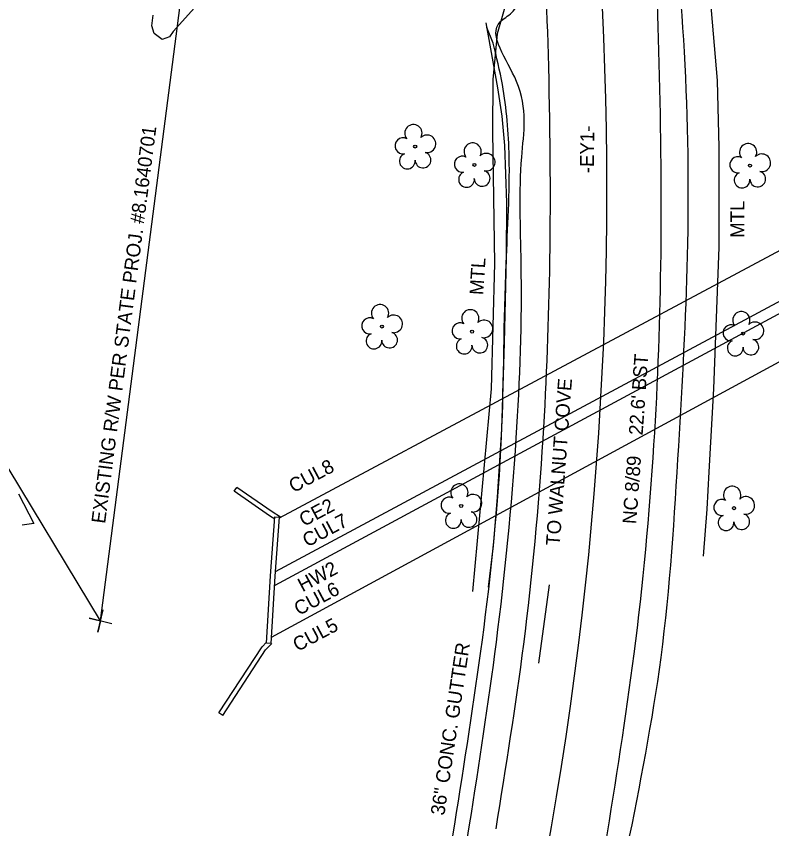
# Model space of a CAD drawing. Extents: x 1645945 to 2447332, y 713118 to 970361.
# Drawn here: x 1646189.7 to 1646352.4, y 969127.2 to 969302.2 of the extents above; entities that cross this region are included whole.
import ezdxf

# ---------------------------------------------------------------- set-up
doc = ezdxf.new("R2010")
doc.units = 0
for name, color, linetype in [('Exist Guardrail', 7, 'Continuous'), ('Exist Guardrail Text', 7, 'Continuous'), ('Exist Horizontal Alignment', 7, 'Continuous'), ('Exist Horizontal Alignment Direction Label', 7, 'Continuous'), ('Exist Property Corner CELL', 7, 'Continuous'), ('Exist Property Line', 7, 'Continuous'), ('Exist Property Line Leader', 7, 'Continuous'), ('Exist Right of Way Line', 7, 'Continuous'), ('Exist Right of Way Line Text', 7, 'Continuous'), ('Exist Roads Curbs', 7, 'Continuous'), ('Exist Roads Curbs Text', 7, 'Continuous'), ('Exist Roads EOP', 7, 'Continuous'), ('Exist Roads EOT', 7, 'Continuous'), ('Exist Roads EOT Leader', 7, 'Continuous'), ('Exist Roads EOT Text', 7, 'Continuous'), ('Exist Structure Major Box Culvert or Tunnel Topo', 7, 'Continuous'), ('Exist Structure Major Bridge WW', 7, 'Continuous'), ('Exist Structure Major Bridge WW Text', 7, 'Continuous'), ('Exist Utilities Telephone UG FO SUE LOS C', 7, 'Continuous'), ('Exist Vegetation Tree CELL', 7, 'Continuous'), ('Exist Vegetation Woods Line', 7, 'Continuous')]:
    doc.layers.add(name, color=color, linetype=linetype)

msp = doc.modelspace()

# ---------------------------------------------------------------- linework, layer by layer
at = {"layer": 'Exist Guardrail'}
for points in [[(1646337.72, 969322.79), (1646339.59, 969300.91), (1646340.61, 969288.29), (1646341.03, 969273.88), (1646340.98, 969252.4), (1646339.88, 969221.89), (1646338.83, 969204.07), (1646338.44, 969196.02), (1646337.61, 969185.9)], [(1646291.41, 969179.21), (1646292.46, 969188.08), (1646293.35, 969198.61), (1646294.24, 969213.19), (1646294.85, 969231.85), (1646295.28, 969250.3), (1646295.35, 969261.96), (1646294.88, 969274.32), (1646294.34, 969280.63), (1646293.4, 969286.73), (1646290.88, 969300.77)]]:
    msp.add_lwpolyline(points, dxfattribs=at)
at = {"layer": 'Exist Horizontal Alignment'}
msp.add_arc((1645516.89, 969265.29), 800, 348.6692, 18.755, dxfattribs=at)
at = {"layer": 'Exist Property Corner CELL'}
msp.add_line((1646207.84, 969171.93), (1646207.84, 969171.93), dxfattribs=at)
msp.add_lwpolyline([(1646210.27, 969171.33), (1646205.41, 969172.53), (1646207.84, 969171.93), (1646207.24, 969169.5), (1646208.44, 969174.36)], dxfattribs=at)
at = {"layer": 'Exist Property Line'}
msp.add_line((1646207.84, 969171.93), (1646184.77, 969210.1), dxfattribs=at)
at = {"layer": 'Exist Property Line Leader'}
msp.add_lwpolyline([(1646190.2, 969199.33), (1646193.51, 969192.93), (1646190.96, 969192.56)], dxfattribs=at)
at = {"layer": 'Exist Right of Way Line'}
msp.add_line((1646207.84, 969171.93), (1646236.81, 969395.79), dxfattribs=at)
msp.add_line((1646207.84, 969171.93), (1646236.81, 969395.79), dxfattribs=at)
msp.add_line((1646207.84, 969171.93), (1646236.81, 969395.79), dxfattribs=at)
msp.add_line((1646207.84, 969171.93), (1646236.81, 969395.79), dxfattribs=at)
at = {"layer": 'Exist Roads Curbs'}
for p, q in [((1646292.43, 969296.35), (1646291.07, 969299.73)), ((1646282.51, 969118.14), (1646284.14, 969128.2))]:
    msp.add_line(p, q, dxfattribs=at)
msp.add_spline([(1646284.14, 969128.2), (1646290.07, 969167.89), (1646294.19, 969211.57), (1646295.19, 969248.95), (1646295.85, 969271.86), (1646294.38, 969287.43), (1646292.43, 969296.35)], degree=3, dxfattribs=at)
at = {"layer": 'Exist Roads EOP'}
msp.add_line((1646285.57, 969117.57), (1646287.33, 969128.01), dxfattribs=at)
for points in [[(1646287.33, 969128.01), (1646293.09, 969167.33), (1646297.37, 969211.3), (1646298.43, 969249.08), (1646298.55, 969271.82), (1646297.44, 969288.13), (1646293.89, 969300.95), (1646296.41, 969302.95), (1646298.17, 969306.12), (1646298.27, 969332.13), (1646295.51, 969374.21), (1646289.77, 969414.06), (1646284.35, 969440.07), (1646274.28, 969480.08), (1646260.88, 969521.84), (1646237.07, 969568.06), (1646226.33, 969574.21), (1646210.08, 969580.6)], [(1646379.88, 969432.02), (1646359.09, 969426.37), (1646353.34, 969423.7), (1646346.05, 969418.75), (1646333.89, 969406.7), (1646326.81, 969393.02), (1646325.09, 969385.45), (1646325.5, 969379.16), (1646330.03, 969336.13), (1646333.52, 969294.46), (1646334.18, 969250.57), (1646332.28, 969209.59), (1646328.48, 969164.09), (1646321.21, 969122.91)]]:
    msp.add_spline(points, degree=3, dxfattribs=at)
at = {"layer": 'Exist Roads EOT'}
for points in [[(1646352.39, 969425.32), (1646344.68, 969420.87), (1646331.6, 969408.76), (1646323.81, 969394.56), (1646321.79, 969386.09), (1646321.5, 969379.49), (1646325.71, 969335.59), (1646328.02, 969294.74), (1646328.47, 969250.99), (1646326.96, 969209.87), (1646322.68, 969164.82), (1646316.52, 969123.72)], [(1646293.03, 969127.18), (1646298.98, 969166.96), (1646303.15, 969211.21), (1646304.61, 969249.63), (1646304.29, 969293.94), (1646302.47, 969332.58), (1646298.43, 969374.41), (1646292.35, 969414.45)]]:
    msp.add_spline(points, degree=3, dxfattribs=at)
at = {"layer": 'Exist Roads EOT Leader'}
msp.add_line((1646302.24, 969162.81), (1646304.56, 969179.68), dxfattribs=at)
at = {"layer": 'Exist Structure Major Box Culvert or Tunnel Topo'}
for p, q in [((1646246.39, 969194.17), (1646400.28, 969276.43)), ((1646245.55, 969182.6), (1646399.69, 969265.26)), ((1646399.55, 969262.69), (1646245.35, 969179.57)), ((1646244.67, 969168.45), (1646399, 969252.16))]:
    msp.add_line(p, q, dxfattribs=at)
at = {"layer": 'Exist Structure Major Bridge WW'}
for p, q in [((1646236.6, 969199.86), (1646237.17, 969200.68)), ((1646245.4, 969194.36), (1646246.4, 969194.29)), ((1646244.59, 969167.1), (1646243.59, 969167.16)), ((1646234.19, 969151.59), (1646233.35, 969152.13))]:
    msp.add_line(p, q, dxfattribs=at)
for points in [[(1646246.63, 969194.27), (1646244.81, 969195.4), (1646237.17, 969200.68)], [(1646245.36, 969193.88), (1646244.26, 969194.57), (1646236.6, 969199.86)], [(1646243.59, 969167.16), (1646244.48, 969181.65), (1646245.4, 969194.36)], [(1646244.59, 969167.1), (1646245.47, 969181.58), (1646246.4, 969194.29)], [(1646233.35, 969152.13), (1646242.62, 969166.38), (1646243.6, 969167.34)], [(1646234.19, 969151.59), (1646243.4, 969165.74), (1646244.77, 969167.09)]]:
    msp.add_lwpolyline(points, dxfattribs=at)
at = {"layer": 'Exist Utilities Telephone UG FO SUE LOS C'}
msp.add_lwpolyline([(1646280.35, 969448.45), (1646284.77, 969427.42), (1646292.91, 969380.8), (1646296.99, 969335.53), (1646294.79, 969303.6), (1646293.24, 969298.34), (1646292.34, 969288.54), (1646292.24, 969277.3), (1646292.7, 969248.91), (1646291.99, 969221.91), (1646287.95, 969178.26)], dxfattribs=at)
at = {"layer": 'Exist Vegetation Tree CELL'}
for p, q in [((1646275.6, 969274.1), (1646275.6, 969274.1)), ((1646288.36, 969270.14), (1646288.36, 969270.14)), ((1646347.7, 969270.01), (1646347.7, 969270.01)), ((1646268.43, 969235.33), (1646268.43, 969235.33)), ((1646287.87, 969234.24), (1646287.87, 969234.24)), ((1646346.22, 969233.82), (1646346.22, 969233.82)), ((1646285.51, 969196.7), (1646285.51, 969196.7)), ((1646344.26, 969196.22), (1646344.26, 969196.22))]:
    msp.add_line(p, q, dxfattribs=at)
for centre in [(1646275.6, 969274.1), (1646288.36, 969270.14), (1646347.7, 969270.01), (1646268.43, 969235.33), (1646287.87, 969234.24), (1646346.22, 969233.82), (1646285.51, 969196.7), (1646344.26, 969196.22)]:
    msp.add_circle(centre, 0.326, dxfattribs=at)
for centre, radius, start, end in [((1646275.22, 969276.97), 1.86, 330.1651, 219.7134), ((1646273, 969274.25), 1.73, 62.6636, 279.3457), ((1646278.15, 969274.68), 1.9, 257.1011, 134.1999), ((1646287.98, 969273.02), 1.86, 330.1651, 219.7134), ((1646347.31, 969272.89), 1.86, 330.1651, 219.7134), ((1646273.9, 969270.97), 1.69, 111.5671, 6.231), ((1646277.28, 969271.2), 1.7, 181.2822, 74.56), ((1646290.91, 969270.73), 1.9, 257.1011, 134.1999), ((1646350.25, 969270.6), 1.9, 257.1011, 134.1999), ((1646285.76, 969270.3), 1.73, 62.6636, 279.3457), ((1646345.09, 969270.17), 1.73, 62.6636, 279.3457), ((1646290.04, 969267.24), 1.7, 181.2822, 74.56), ((1646286.66, 969267.02), 1.69, 111.5671, 6.231), ((1646346, 969266.89), 1.69, 111.5671, 6.231), ((1646349.37, 969267.11), 1.7, 181.2822, 74.56), ((1646268.04, 969238.2), 1.86, 330.1651, 219.7134), ((1646270.98, 969235.91), 1.9, 257.1011, 134.1999), ((1646287.48, 969237.11), 1.86, 330.1651, 219.7134), ((1646345.84, 969236.69), 1.86, 330.1651, 219.7134), ((1646265.82, 969235.48), 1.73, 62.6636, 279.3457), ((1646285.26, 969234.39), 1.73, 62.6636, 279.3457), ((1646290.42, 969234.83), 1.9, 257.1011, 134.1999), ((1646343.62, 969233.97), 1.73, 62.6636, 279.3457), ((1646348.77, 969234.41), 1.9, 257.1011, 134.1999), ((1646270.1, 969232.43), 1.7, 181.2822, 74.56), ((1646266.73, 969232.21), 1.69, 111.5671, 6.231), ((1646286.16, 969231.12), 1.69, 111.5671, 6.231), ((1646289.54, 969231.34), 1.7, 181.2822, 74.56), ((1646344.52, 969230.7), 1.69, 111.5671, 6.231), ((1646347.9, 969230.92), 1.7, 181.2822, 74.56), ((1646285.13, 969199.58), 1.86, 330.1651, 219.7134), ((1646343.87, 969199.09), 1.86, 330.1651, 219.7134), ((1646288.06, 969197.29), 1.9, 257.1011, 134.1999), ((1646282.91, 969196.86), 1.73, 62.6636, 279.3457), ((1646341.65, 969196.37), 1.73, 62.6636, 279.3457), ((1646346.81, 969196.81), 1.9, 257.1011, 134.1999), ((1646287.19, 969193.8), 1.7, 181.2822, 74.56), ((1646283.81, 969193.58), 1.69, 111.5671, 6.231), ((1646342.55, 969193.1), 1.69, 111.5671, 6.231), ((1646345.93, 969193.32), 1.7, 181.2822, 74.56)]:
    msp.add_arc(centre, radius, start, end, dxfattribs=at)
at = {"layer": 'Exist Vegetation Woods Line'}
msp.add_lwpolyline([(1646228.73, 969304.68), (1646223.51, 969298.9), (1646222.69, 969297.7), (1646221.1, 969297.18), (1646219.39, 969298.43), (1646218.87, 969300.1), (1646219.17, 969302.4)], dxfattribs=at)

# ---------------------------------------------------------------- texts
at = {"layer": 'Exist Guardrail Text'}
for rotation, p in [(89.8681, (1646346.48, 969254.43)), (86.51, (1646290.28, 969242.06))]:
    msp.add_text('MTL', height=3, rotation=rotation, dxfattribs=at).set_placement(p)
at = {"layer": 'Exist Horizontal Alignment Direction Label'}
msp.add_text('-EY1-', height=3, rotation=89.2798, dxfattribs=at).set_placement((1646314.07, 969268.34))
at = {"layer": 'Exist Right of Way Line Text'}
msp.add_text('EXISTING R/W PER STATE PROJ. #8.1640701', height=3, rotation=82.626, dxfattribs=at).set_placement((1646208.83, 969192.79))
at = {"layer": 'Exist Roads Curbs Text'}
msp.add_text('36" CONC. GUTTER', height=3, rotation=81.507, dxfattribs=at).set_placement((1646281.87, 969129.92))
at = {"layer": 'Exist Roads EOT Text'}
for s, rotation, p in [("NC 8/89    22.6' BST", 85.9207, (1646323.22, 969192.73)), ('TO WALNUT COVE', 85.7728, (1646306.73, 969188.04))]:
    msp.add_text(s, height=3, rotation=rotation, dxfattribs=at).set_placement(p)
at = {"layer": 'Exist Structure Major Bridge WW Text'}
for s, p in [('CUL8', (1646249.41, 969199.44)), ('CE2', (1646251.64, 969192.17)), ('CUL7', (1646252.37, 969187.74)), ('HW2', (1646251.34, 969178.09)), ('CUL6', (1646250.55, 969173.01)), ('CUL5', (1646250.28, 969165.25))]:
    msp.add_text(s, height=3, rotation=28.1451, dxfattribs=at).set_placement(p)

doc.saveas('drawing.dxf')
